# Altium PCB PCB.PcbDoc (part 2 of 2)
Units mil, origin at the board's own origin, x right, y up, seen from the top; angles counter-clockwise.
Board outline 3149.61 x 1968.5 mil, 4 copper layers (Top, GND, Power, Bottom), stack 59.37 mil thick; 127 components, 80 nets, 529 pads, 122 vias.
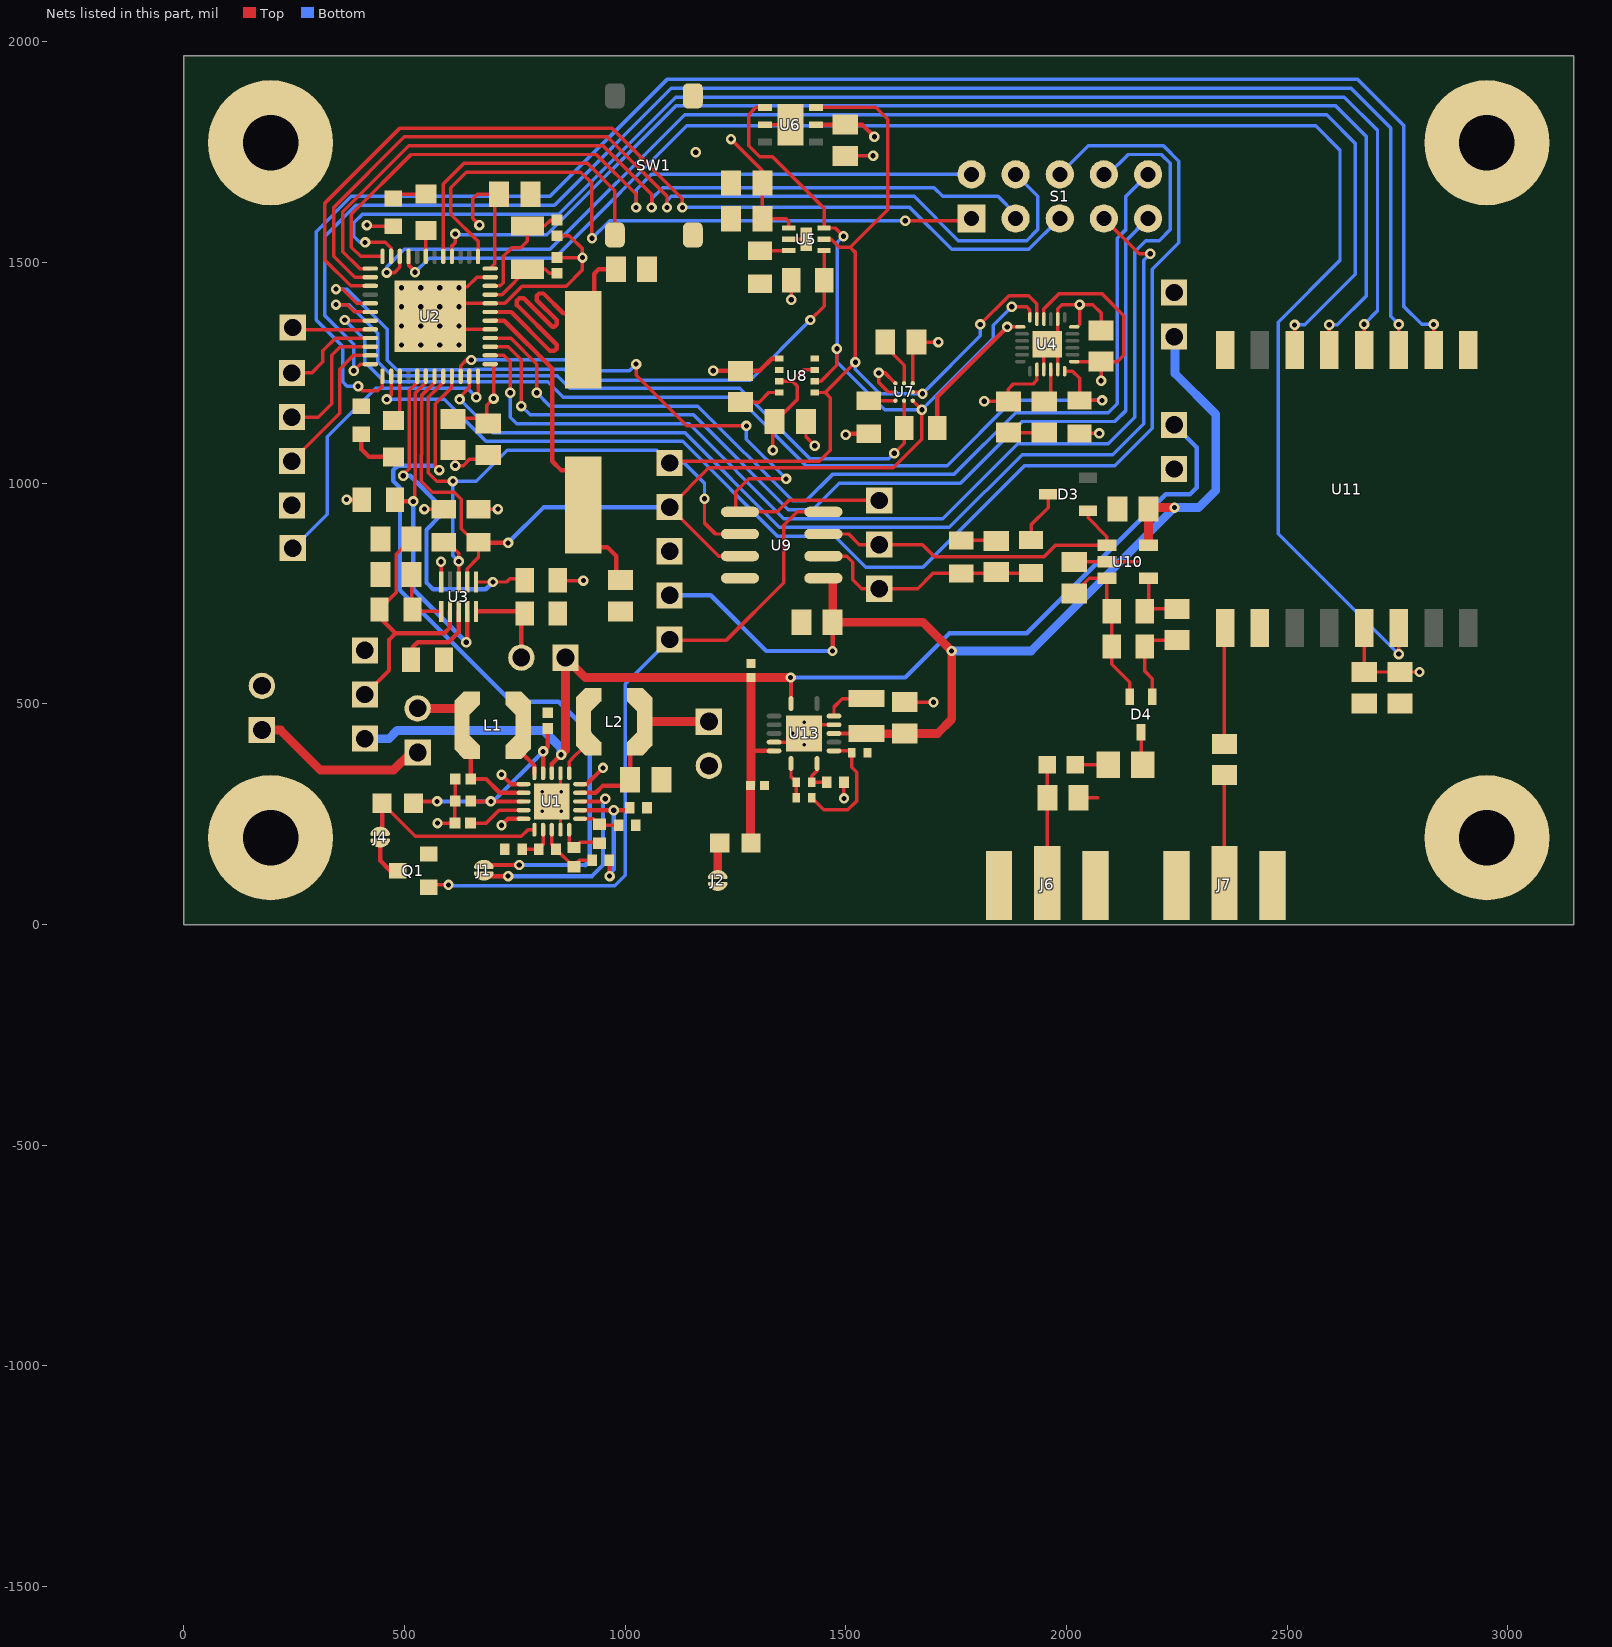
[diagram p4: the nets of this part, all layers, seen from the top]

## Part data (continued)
Rcg1: library part CMP-00129-1, "RES SMD 0.05 OHM 1% 1/3W 0805", Manufacturer="Rohm Semiconductor", Operating Temperature="-55°C ~ 155°C", Package / Case="0805 (2012 Metric)", Power (Watts)="0.333W, 1/3W", Resistance (Ohms)=0.05, Supplier Part Number=RHM1293CT-ND, Temperature Coefficient="0/ +150ppm/°C", Tolerance=±1%
S1: "SIP-5x2 2.54mm 2-row"
SW1: library part CMP-00033-1, "Switch, SPNO Push Button SMD", Manufacturer=APEM
U1: library part CMP-00082-2, "IC ENERGY HARV CTRLR BATT 20VQFN", Current - Supply=488nA, Manufacturer="Texas Instruments", Operating Temperature="-40°C ~ 125°C", Package / Case="20-VFQFN Exposed Pad", Supplier Device Package="20-VQFN (3.5x3.5)", Supplier Part Number=296-37014-2-ND, Voltage - Supply="0.12 V ~ 4 V"
U2: library part CMP-00055-1, "IC MCU 16BIT 64KB FRAM 48VQFN", Manufacturer="Texas Instruments", Operating Temperature="-40°C ~ 85°C (TA)", Package / Case="48-VFQFN Exposed Pad", Supplier Device Package="48-VQFN (7x7)", Supplier Part Number=296-37918-6-ND, Voltage - Supply (Vcc/Vdd)="1.8 V ~ 3.6 V"
U3: library part CMP-00128-1, "IC GAS GAUGE ALARM OUTPUT 10DFN", Manufacturer=STMicroelectronics, Operating Temperature="-40°C ~ 85°C (TA)", Package / Case=10-UFDFN, Supplier Device Package="10-DFN (3x2)", Supplier Part Number=497-15078-2-ND
U4: library part CMP-00238-1, "Accelerometer, Gyroscope, Magnetometer, 3 Axis Sensor I²C, SPI Output", Manufacturer=InvenSense, Operating Temperature="-40°C ~ 85°C (TA)", Supplier Part Number=1428-1019-1-ND
U5: library part CMP-00134-1, "INTEGRATED DIGITAL AMBIENT LIGHT SENSOR WITH INTERRUPT FUNCTION, ODFN-6", Manufacturer=Intersil, Operating Temperature="-40°C ~ 85°C", Package / Case="6-WDFN Exposed Pad", Supplier Device Package="6-ODFN (2.1x2)", Supplier Part Number=ISL29023IROZ-T7TR-ND, Voltage - Supply="2.25 V ~ 3.63 V"
U6: library part CMP-00136-1, "HUMIDITY/TEMPERATURE SENSOR, Accuracy %:2%, Supply Voltage:3V, Humidity Range:0% to 100% Relative Humidity, Sensor Case Style:DFN, No. of Pins:6, Response Time:8s, Operating Temperature Min:-40 C, Operating Temperature Max:125 C , RoHS Compliant", Manufacturer="Sensirion AG", Operating Temperature="-40°C ~ 125°C", Supplier Part Number=1649-1005-2-ND, Voltage - Supply="2.1 V ~ 3.6 V"
U7: library part CMP-0978-00003-2, "Infrared Thermopile Sensor, 2.2 to 3.6 V, 240 uA, -40 to 125 degC, 8-Pin BGA (YZF8), Green (RoHS & no Sb/Br), Tape and Reel", Manufacturer="Texas Instruments", Supply Current (Typ)="240 uA", Supply Voltage="2.2 to 3.6 V", Temperature Range="-40 to 125 degC", Temp Resolution (Max)="14 Bit", Two-Wire Interface Voltage="1.8 V"
U8: library part CMP-00278-1, "PRESSURE HUMIDITY TEMP GAS SENS", Manufacturer="Bosch Sensortec", Operating Pressure="4.35 PSI ~ 15.95 PSI (30 kPa ~ 110 kPa)", Operating Temperature="-40°C ~ 85°C", Package / Case=8-SMD, Supplier Part Number=828-1063-2-ND, Voltage - Supply="1.71 V ~ 3.6 V"
U9: library part CMP-00130-1, "IC MCU 8BIT 3.5KB FLASH 8SOIC", Manufacturer="Microchip Technology", Operating Temperature="-40°C ~ 85°C (TA)", Supplier Device Package=8-SOIC, Supplier Part Number=PIC12LF1552-I/SN-ND, Voltage - Supply (Vcc/Vdd)="1.8 V ~ 3.6 V"
U10: library part CMP-00131-1, "IC OUT COMPARATR NANOPWR SOT23-5", Current - Input Bias (Max)="250pA @ 15V", Current - Output (Typ)=10mA, Current - Quiescent (Max)=1µA, Manufacturer="Texas Instruments", Operating Temperature="0°C ~ 70°C", Package / Case="SC-74A, SOT-753", Supplier Device Package=SOT-23-5, Supplier Part Number=296-13377-2-ND, Voltage - Input Offset (Max)="5mV @ 15V", Voltage - Supply, Single/Dual (±)="2.5 V ~ 16 V, ±1.25 V ~ 8 V"
U11: library part CMP-00138-2, "RF TXRX MODULE ISM<1GHZ", Current - Receiving="10.8mA ~ 12.1mA", Current - Transmitting="20mA ~ 120mA", Frequency=868MHz, Manufacturer="RF Solutions", Operating Temperature="-20°C ~ 70°C", Package / Case="16-SMD Module", Power - Output=17dBm, Supplier Part Number=RFM95W-868S2-ND, Voltage - Supply="1.8 V ~ 3.7 V"
U13: library part CMP-00239-2, "Buck Switching Regulator IC Positive Programmable 1.3V 1 Output 50mA 14-VFQFN Exposed Pad", Current - Output=50mA, Frequency - Switching=2MHz, Manufacturer="Texas Instruments", Operating Temperature="-40°C ~ 85°C (TA)", Package / Case="14-VFQFN Exposed Pad", Supplier Device Package="14-VQFN (3.5x3.5)", Supplier Part Number=296-43622-1-ND, Voltage - Input (Max)=5.5V, Voltage - Input (Min)=2V, Voltage - Output (Max)=5V, Voltage - Output (Min/Fixed)=1.3V
X1 X2 X3 X4 X5 X6 X9 X10 X11 X12 X13 X14 X15 X16 X21 X22 X23: library part CMP-00008-1, "Terminal Assembly, 1 Pin, Vertical, 2.54mm Pitch, Male", Manufacturer=Samtec, Temperature Range="-55 to 125 degC"
X18 X25 X27 X28: library part CMP-00008-2, "Conn Unshrouded Header HDR 1 POS Vertical Solder ST Thru-Hole", Color=Black, Manufacturer="Amphenol FCI", Manufacturer Part Number=68001-101HLF, Supplier Part Number=609-3467-ND
Y1: library part CMP-0447-00001-2, "Crystal, 32.768 kHz, 12.5 pF, -40 to 85 degC, SMD Low Profile 3.2 x 1.5 x 0.9 mm, Tape and Reel", Equivalent Series Resistance (R1)="70 Kohm", Frequency="32.768 kHz", Frequency Tolerance @+25degC="+/- 20 ppm", Insulation Resistance (Min)="500 Mohm", Load Capacitance (CL)="12.5 pF", Manufacturer=Abracon, Operating Temperature="-40 to 85 degC", Q Value (Type)=30000, Shunt Capacitance (C0)="0.9 to 1.2 pF"
Y2: library part CMP-0277-00002-1, "Low Profile Surface Mount Microprocessor Crystal, 4.096 MHz +/-30 ppm, 180 Ohm, -40 to 85 degC, 2-Pin 11.4 x 4.7 x 3.3 mm SMD, RoHS, Tape and Reel", Freq. Stability="+/- 30 ppm", Frequency="4.096 MHz", Load Capacitance="18 pF", Manufacturer=Abracon, Operating Temp. Range="-40 to 85 degC", Shunt Capacitance="7 pF Max."

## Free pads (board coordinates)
  round 0 all layers, no hole paste+0 mask+0: 1(2736.74,-1512.59) 1(2736.74,-1512.59)

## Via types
v1: diameter 23.62, hole 11.81, Top to Bottom, tented both sides, 94 vias
v2: diameter 27.56, hole 11.81, Top to Bottom, tented both sides, 16 vias
v3: diameter 19.68, hole 7.87, Top to Bottom, tented both sides, 8 vias
v4: diameter 23.62, hole 11.81, Top to Bottom, 4 vias

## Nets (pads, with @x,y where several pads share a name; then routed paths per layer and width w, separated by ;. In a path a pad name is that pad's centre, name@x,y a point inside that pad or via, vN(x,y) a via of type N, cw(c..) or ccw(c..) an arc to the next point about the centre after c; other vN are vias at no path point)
ALM: R11.2 U2.29 U3.1 | length 814.3
  Top w7.87: v1(497.23,1016.91) 497.23,1019.12 497.19,1019.16 510.68,1032.65 510.68,1075.29 511.06,1075.66 511.06,1210.45 529,1228.39 U2.29@529,1242.51 ; U3.1@662.24,776.3 v1(700.61,776.3) 731.35,776.3 739.05,784 R11.2@769.6,784
  Bottom w7.87: v1@497.19,1013.11 497.23,1013.15 v1(497.23,1016.91)
  Bottom w10: v1(497.23,1016.91) 513.09,1016.91 579.55,950.45 579.55,924.55 550,895 550,775 565,760 684.31,760 v1(700.61,776.3)
BAT+: C39.2 C40.2 R21.1 U1.18 U13.1 U13.6 X7.1 X23.1 X27.1 | length 3037.4
  Top w10: U1.18@834.05,343.01 834.05,364.05 v1(855,385) ; 1285,395 1286.3,393.7 U13.6@1337.6,393.7 ; v4(1375,560) 1375.98,559.02 U13.1@1375.98,500.98
  Top w20: v1(855,385) 865,395 X7.1@865,605 910,560 C40.2@1285,560 ; R21.1@1285.43,185 1284.25,186.18 C39.2@1284.25,315 1285,315.75 1285,395 C40.2@1285,560 ; v4(1375,560) C40.2@1285,560
  Bottom w10: v4(1375,560) 1635,560 1735,660 1910,660 2225,975 2280,975 2295,990 2295,1081.38 X27.1@2244.09,1132.28
  Bottom w20: X23.1@410.24,421.26 465,421.26 483.74,440 815,440 855,400 v1(855,385)
BAT-: Rcg1.2 U3.10 X7.2 | length 238.5
  Top w10: U3.10@662.24,709.76 767.83,709.76 Rcg1.2@772.6,705 765,697.4 X7.2@765,605 765,595.63 X7.2@755.31,605.31
BUCK_EN: Q1.1 U9.4 X16.1 | length 1579.9
  Top w7.87: Q1.1@555,85 560,90 v1(600,90) ; X16.1@1100.92,646.05 1100.92,644.84 1229.84,644.84 1360,775 1360,905.14 1389.91,935.06 U9.4@1449.4,935.06
  Bottom w7.87: v1(600,90) 601.75,88.25 976.75,88.25 1000,111.5 1000,545.13 X16.1@1100.92,646.05
DATA: D3.1 U9.3 U10.1 X10.1 | length 769.7
  Top w7.87: U9.3@1449.4,885.06 1506.91,885.06 1530.91,861.06 X10.1@1575.91,861.06 1673.91,861.06 1700.91,834.06 1949.91,834.06 1975.31,859.46 U10.1@2091.67,859.46 2091.67,879.3 2049.19,921.78 D3.1@2049.19,937.65
GND: C1.1 C2.1 C3.1 C4.1 C5.1 C6.1 C7.1 C8.1 C9.2 C10.2 C11.1 C12.1 C13.2 C14.1 C15.2 C16.1 C17.1 C18.2 C19.1 C22.2 C25.2 C26.2 C27.2 C28.1 C29.1 C31.1 C32.1 C33.1 C34.1 C35.2 C36.2 C39.1 C40.1 C41.1 D4.1 J2.2 J6.2 J6.3 J6.4 J6.5 J7.2 J7.3 J7.4 J7.5 M1.1 M2.1 M3.1 M4.1 Q1.2 R5.1 R6.1 R7.1 R8.2 R9.2 R15.1 R19.1 R25.1 R26.1 R32.1 R33.1 Rcg1.1 SW1.1 SW1.2 U1.1 U1.5 U1.9 U1.15 U1.17 U1.21 U2.36 U2.41 U2.44 U2.47 U2.49 U3.5 U4.9 U4.11 U4.18 U4.20 U4.25 U5.2 U5.7 U6.2 U6.7 U7.A1 U7.A2 U7.B1 U8.1 U8.5 U8.7 U9.8 U10.2 U11.1 U11.8 U11.10 U13.5 U13.12 U13.15 X6.1 X8.2 X14.1 X28.1 | length 3919
  Top w7.87: v1(415,1585) 417.72,1582.28 R8.2@474.53,1582.28 ; U2.49@558.53,1378.34 U2.49@588.05,1407.87 ; v1(575,230) C3.1@614.57,230 614.57,279.57 C2.1@615,280 C4.1@615,330 ; v1(583,822) 583,776.8 U3.5@583.5,776.3 ; U2.49@588.05,1348.81 U2.41@694.35,1348.81 ; C8.1@606.67,1091.34 615,1083.01 v1(615,1040) 633,1040 647,1054 673,1054 C7.1@687,1068 ; v2(623.49,1443.3) U2.49@588.05,1407.87 ; U2.49@625.19,1445 642.49,1445 664.41,1466.92 U2.47@694.35,1466.92 ; v1(663,1195) 666.79,1198.79 U2.36@666.79,1242.51 ; U1.1@770.07,317.42 U1.1@770.07,318.4 ; C9.2@845.81,1511.49 v1(903.51,1511.49) ; C10.2@845.81,1561.05 873.81,1561.05 903.51,1531.35 v1(903.51,1511.49) ; U1.9@853.73,215.06 U1.21@853.73,259.35 ; U1.21@853.73,298.72 U1.17@853.73,343.01 ; U1.15@898.02,317.42 U1.15@898.02,318.4 ; C27.2@1261.87,1184 1304,1184 1325.71,1205.71 U8.5@1349.41,1205.71 ; U6.2@1317.39,1812.43 U6.7@1374.87,1812.43 ; U13.5@1337.6,413.39 U13.15@1385.82,413.39 ; U8.7@1344.35,1256.89 U8.7@1349.41,1256.89 ; U5.2@1370.89,1552.87 U5.7@1410.85,1552.87 ; C26.2@1410,1140 1410,1105 v1(1430,1085) ; U13.15@1425.19,452.76 U13.12@1473.42,452.76 ; v1(1496.06,286.06) R33.1@1496.06,322.84 ; C25.2@1498.87,1742 v1(1562,1742) ; C22.2@1589.57,1320 1589.57,1310.43 1632.21,1267.79 U7.A2@1632.21,1226.56 ; U7.B1@1612.53,1206.87 1596.43,1206.87 1575,1228.31 v1(1575,1250) 1589.09,1250 U7.A1@1612.53,1226.56 ; C41.1@1633.86,503.94 v1(1698.94,503.94) ; R25.1@1761.91,870.46 1839.94,870.46 C31.1@1840.91,869.49 ; C15.2@1868.87,1115 C19.1@1950.05,1115 ; U4.9@1948.82,1257.87 1948.82,1307.09 U4.25@1956.69,1314.96 U4.25@1962.6,1320.87 ; U4.11@1980.32,1257.87 1980.32,1303.15 U4.25@1962.6,1320.87 ; U4.18@2017.72,1354.33 2024.33,1354.33 2030,1360 v4(2030,1405) ; C34.1@2017.91,821.49 C34.1@2020.51,818.9 ; C34.1@2018.48,822.06 U10.2@2091.67,822.06 2161.63,822.06 ; C32.1@2027.56,287.4 2070.87,287.4 ; C16.1@2078.74,1346.46 2078.74,1385.83 2059.57,1405 v4(2030,1405) ; C29.1@2115.48,942.06 C29.1@2118.11,944.69 ; D4.1@2194.88,516.73 2194.88,557.09 2177.4,574.57 R26.1@2177.4,630 2192.03,644.62 C33.1@2250.91,644.62 ; U11.10@2437.01,673.02 U11.10@2438.4,671.62 ; U2.49@588.05,1407.87 U2.44@694.35,1407.87 727.87,1407.87 766.49,1446.49 866.49,1446.49 903.51,1483.51 v1(903.51,1511.49) ; U4.25@1962.6,1320.87 1980.32,1338.58 U4.20@1980.32,1372.05 1980.32,1395.31 1990,1405 v4(2030,1405)
  Top w10: v1(720,225) 734.66,239.66 U1.5@770.07,239.66 ; v1(720,340) 741.6,318.4 U1.1@770.07,318.4 ; U1.15@898.02,318.4 913.4,318.4 v1(950,355)
  Bottom w7.87: X6.1@247,853 248,853 325,930 325,1105 435,1215 643,1215 v1(663,1195)
  other v1: 1160,1750
  other v2: 493.57,1313.38 536.87,1313.38 580.18,1313.38 623.49,1313.38 493.57,1356.69 536.87,1356.69 580.18,1356.69 623.49,1356.69 493.57,1399.99 536.87,1399.99 580.18,1399.99 623.49,1399.99 493.57,1443.3 536.87,1443.3 580.18,1443.3
  other v3: 812.39,257.38 855.7,257.38 812.39,300.69 855.7,300.69 1405.51,407.48 1379.92,433.07 1431.1,433.07 1405.51,458.66
HIGHFCLOCK_IN: C11.2 U2.42 Y2.1 | length 722.9
  Top w10: U2.42@694.35,1368.5 726.5,1368.5 835,1260 835,1050 855,1030 Y2.1@910,1030 ; Y2.1@875.98,980 Y2.1@905,950.98 Y2.1@905,905 ; Y2.1@890,855 960,855 980,835 980,790.43 C11.2@990,780.43
HIGHFCLOCK_OUT: C12.2 U2.43 Y2.2 | length 889.4
  Top w10: U2.43@694.35,1388.18 741.82,1388.18 830,1300 840,1300 845,1305 845,1313.88 755,1403.88 755,1413.88 760.56,1419.44 770.56,1419.44 835,1355 840,1355 845,1360 845,1370 800,1415 800,1425 805,1430 815,1430 860,1385 Y2.2@915,1385 ; Y2.2@905,1325 930,1350 930,1475 940,1485 C12.2@979.13,1485
LORA_DIO0: U2.9 U11.14 | length 3672.6
  Top w7.87: U2.9@509.31,1514.17 509.31,1494.56 524,1479.87 v1(524,1478) ; v1@2753,610.8 v1(2753,613) 2753.36,613.36 U11.14@2753.36,671.62
  Bottom w7.87: v1(524,1478) 556,1510 840,1510 1140,1810 2565,1810 2620,1755 2620,1505 2480,1365 2480,886 v1(2753,613)
LORA_RESET: U2.10 U11.6 | length 2975.6
  Top w7.87: v1(460,1477.49) 477.49,1477.49 489.63,1489.63 U2.10@489.63,1514.17 ; U11.6@2517.14,1301.54 v1(2517.14,1358.86)
  Bottom w7.87: v1(460,1477.49) 460,1490 500,1530 830,1530 1135,1835 2590,1835 2655,1770 2655,1473.74 2540.12,1358.86 v1(2517.14,1358.86)
LOWFCLOCK_IN: C9.1 U2.45 Y1.1 | length 178.9
  Top w7.87: U2.45@694.35,1427.55 721.12,1427.55 Y1.1@778.53,1484.96 819.34,1484.96 828.24,1476.06 C9.1@845.81,1476.06
LOWFCLOCK_OUT: C10.1 U2.46 Y1.2 | length 268.3
  Top w7.87: U2.46@694.35,1447.24 716.56,1447.24 724.12,1454.8 724.12,1514.17 743.72,1533.77 763.53,1533.77 778.53,1548.77 Y1.2@778.53,1583.39 818.14,1583.39 831.24,1596.49 C10.1@845.81,1596.49
NetC3_2: C3.2 U1.4 | length 132.2
  Top w7.87: C3.2@650,230 685,230 714.35,259.35 U1.4@770.07,259.35
NetC4_2: C4.2 H_IN.2 L1.1 U1.2 | length 328.4
  Top w7.87: L1.1@629.39,451.03 L1.1@630.39,452.03
  Top w10: L1.1@647.14,405.89 650.43,402.6 C4.2@650.43,330 685,330 716.28,298.72 U1.2@770.07,298.72
  Top w20: H_IN.2@530,490 L1.1@647.14,490
NetC5_2: C5.2 L2.2 U1.14 X19.1 | length 366.8
  Top w10: U1.14@898.02,298.72 933.72,298.72 950,315 998.41,315 C5.2@1011.44,328.03 1011.44,389.23 L2.2@1017.92,395.71
  Top w20: L2.2@1040.36,457.03 1043.33,460 X19.1@1190,460 X19.1@1210,460
NetC13_1: C13.1 R14.1 U3.6 | length 138
  Top w7.87: R14.1@516.31,716 C13.1@516.31,793.03 ; R14.1@522.54,709.76 U3.6@583.5,709.76
NetC14_2: C14.2 R14.2 U3.7 X22.1 | length 592.2
  Top w7.87: R14.2@443.47,714.03 481.87,752.43 481.87,839.6 C14.2@516.31,874.03
  Top w10: X22.1@410.24,521.26 465,576.02 465,645 480,660 ; R14.2@443.47,714.03 443.47,696.53 480,660 ; U3.7@603.19,709.76 603.19,673.19 590,660 480,660
NetC19_2: C19.2 U4.10 | length 77.9
  Top w7.87: C19.2@1964.57,1180 U4.10@1964.57,1257.87
NetC30_1: C30.1 D4.3 | length 73.8
  Top w7.87: C30.1@2169.29,362.2 D4.3@2169.29,436.02
NetC30_2: C30.2 L3.2 | length 78.7
  Top w7.87: L3.2@2019.69,362.2 C30.2@2094.49,362.2 C30.2@2098.43,362.2
NetC32_2: C32.2 J6.1 L3.1 | length 267.7
  Top w7.87: J6.1@1956.69,94.49 C32.2@1956.69,287.4 L3.1@1956.69,362.2
NetC34_2: C34.2 D4.2 R24.2 R26.2 U10.3 | length 377.3
  Top w7.87: C34.2@2017.91,750.62 2051.94,784.65 U10.3@2091.67,784.65 2091.67,720.93 R24.2@2102.6,710 R26.2@2102.6,630 2102.6,590.31 2143.7,549.21 D4.2@2143.7,516.73
NetC38_1: C38.1 J7.1 | length 244.1
  Top w7.87: J7.1@2358.27,94.49 C38.1@2358.27,338.58
NetC38_2: C38.2 U11.9 | length 260.8
  Top w7.87: C38.2@2358.27,409.45 U11.9@2358.27,670.23
NetD1_1: D1.1 R8.1 | length 70.2
  Top w7.87: R8.1@478.46,1655.11 D1.1@548.68,1655.11
NetD1_2: D1.2 U2.7 | length 58.3
  Top w7.87: U2.7@548.68,1514.17 D1.2@548.68,1572.43
NetD2_1: D2.1 R9.1 | length 113.5
  Top w10: R9.1@402.49,1111.28 402.49,1077.51 420,1060 D2.1@475,1060
NetD2_2: D2.2 U2.27 | length 105.9
  Top w7.87: D2.2@475,1142.68 489.63,1157.31 U2.27@489.63,1242.51
NetD3_3: D3.3 R23.1 | length 119.6
  Top w7.87: R23.1@1919.91,871.46 1919.91,906.06 1958.64,944.78 D3.3@1958.64,975.06
NetJ1_1: J1.1 U2.33 | length 1731.4
  Top w8: v1(579,1030) 570,1039 570,1180 607.74,1217.74 U2.33@607.74,1242.51
  Top w10: J1.1@670,134.61 670.39,135 v1(760,135)
  Bottom w10: v1(579,1030) 569,1040 485,1040 474.42,1029.42 474.42,1005.58 490,990 490,757.74 742.74,505 850,505 920,435 920,145 909.61,134.61 909.21,135 v1(760,135)
NetJ1_2: J1.2 U1.13 | length 501.9
  Top w10: J1.2@670,110 J1.2@680,110 v1(735,110) ; U1.13@898.02,279.03 949.03,279.03 v1(955,285)
  Bottom w10: v1(735,110) 925,110 950,135 950,280 v1(955,285)
NetJ2_1: J2.1 R21.2 | length 73.6
  Top w20: J2.1@1210,113.29 1210,180.43 R21.2@1214.57,185
NetJ4_1: J4.1 R20.2 U1.6 | length 447.7
  Top w7.87: J4.1@445,211.57 J4.1@449.57,216.14 ; R20.2@449.57,275 524.57,200 765,200 780.06,215.06 U1.6@794.68,215.06
  Top w10: J4.1@449.57,216.14 R20.2@449.57,275
NetJ4_2: J4.2 Q1.3 | length 89.6
  Top w10: J4.2@445,185.1 J4.2@445,185 445,145 468,122 Q1.3@485,122
NetL1_2: L1.2 U1.20 | length 77.7
  Top w10: L1.2@746.92,390.71 764.29,390.71 794.68,360.32 U1.20@794.68,343.01
NetL2_1: L2.1 U1.16 | length 72.8
  Top w7.87: U1.16@873.42,343.01 873.42,369.23 880.56,376.37 880.56,376.76 L2.1@906.07,402.27
NetL5_1: L5.1 U13.13 | length 102.4
  Top w7.87: U13.13@1473.42,472.44 1473.42,493.11 1492.52,512.21 L5.1@1547.24,512.21
NetR1_1: R1.1 R6.2 U1.12 | length 304.1
  Top w10: U1.12@898.02,259.35 v1(974.35,259.35) 1004.66,259.35 R6.2@1010.31,265 ; R1.1@964.56,146.03 965,145.59 v1(965,110)
  Bottom w10: v1(965,110) 965,116.16 974.35,125.51 v1(974.35,259.35)
NetR1_2: R1.2 R2.2 R3.2 U1.8 | length 134.4
  Top w7.87: R2.2@834.05,180.54 U1.8@834.05,215.06 ; R2.2@843.56,171.03 R3.2@881.24,133.35 ; R3.2@883.87,133.35 896.56,146.03 R1.2@925.19,146.03
NetR2_1: R2.1 R5.2 U1.7 | length 85.9
  Top w7.87: R5.2@766.56,171.03 R2.1@804.19,171.03 814.36,181.21 U1.7@814.36,215.06
NetR3_1: R3.1 R4.2 U1.10 | length 110.2
  Top w7.87: U1.10@873.42,215.06 873.42,183.17 883.87,172.72 897.33,186.17 R4.2@941.87,186.17
NetR4_1: R4.1 R7.2 U1.11 | length 90
  Top w7.87: U1.11@898.02,239.66 927.76,239.66 941.87,225.54 R7.2@982.13,225.54
NetR15_2: R15.2 U3.8 | length 203
  Top w10: R15.2@518.47,591.03 518.47,628.47 530,640 600,640 622.87,662.87 U3.8@622.87,709.76
NetR16_2: R16.2 U7.C1 | length 60.3
  Top w7.87: R16.2@1552.23,1187.19 U7.C1@1612.53,1187.19
NetR17_1: R17.1 U2.19 U4.12 | length 2142.9
  Top w7.87: v1(365,1370) 366.5,1368.5 U2.19@422.7,1368.5 ; U4.12@1996.06,1253.94 2013.78,1253.94 2029.87,1237.84 R17.1@2029.87,1187.83 v1(2080.85,1187.83)
  Bottom w7.87: v1(365,1370) 410,1325 410,1274.83 454.9,1229.94 825.06,1229.94 860,1195 1255,1195 1410,1040 1730,1040 1877.83,1187.83 v1(2080.85,1187.83)
NetR18_1: R18.1 U2.17 U5.4 | length 1519.3
  Top w7.87: v1(345,1440) 360,1440 392.13,1407.87 U2.17@422.7,1407.87 ; v1(1420,1370) 1451.28,1401.28 R18.1@1451.28,1460.43 ; R18.1@1450.81,1460.89 U5.4@1450.81,1527.28
  Bottom w7.87: v1(345,1440) 370,1440 461.19,1348.81 461.19,1278.81 482.31,1257.69 660.36,1257.69 660.68,1258 862,1258 886.75,1233.25 1283.25,1233.25 v1(1420,1370)
NetR19_2: R19.2 U5.3 | length 64.6
  Top w7.87: R19.2@1306.32,1527.28 U5.3@1370.89,1527.28
NetR22_2: R22.2 U2.18 U7.C2 | length 1665.6
  Top w7.87: v1(345,1405) 370.76,1405 387.58,1388.18 U2.18@422.7,1388.18 ; v1(1610,1068) 1632.47,1090.47 R22.2@1632.47,1125.43 ; R22.2@1632.21,1125.69 U7.C2@1632.21,1187.19
  Bottom w7.87: v1(345,1405) 375,1405 440,1340 440,1275 471.19,1243.81 846.19,1243.81 875,1215 1260,1215 1419.13,1055.87 1597.87,1055.87 v1(1610,1068)
NetR30_1: R30.1 R32.2 U13.9 | length 273.6
  Top w7.87: R30.1@1423.23,287.4 1450.63,260 1505,260 1525,280 1525,345 1513.78,356.22 R32.2@1513.78,389.77 ; U13.9@1473.42,393.7 R32.2@1509.85,393.7 ; R32.2@1516.73,386.81 R32.2@1517.72,385.83
NetR30_2: R30.2 R31.2 U13.7 | length 82.6
  Top w7.87: U13.7@1375.98,365.16 1375.98,334.65 R31.2@1387.8,322.84 R30.2@1387.8,287.4
NetR31_1: R31.1 R33.2 U13.8 | length 80.7
  Top w7.87: U13.8@1435.04,365.16 1435.04,348.43 1423.23,336.62 R31.1@1423.23,322.84 R33.2@1456.69,322.84
NetS1_1: S1.1 U2.1 | length 1527
  Top w7.87: U2.1@666.79,1514.17 666.79,1548.21 605,1610 605,1670 640,1705 900,1705 925,1680 v1@925,1565 ; v1(925,1555) v1@930,1560 ; v1(1635,1595) 1780,1595 S1.1@1785,1600
  Bottom w7.87: v1(925,1555) 965,1595 v1(1635,1595)
NetS1_2: S1.2 U2.12 | length 1726.6
  Top w7.87: U2.12@450.26,1514.17 400.83,1514.17 380,1535 380,1610 515,1745 935,1745 1025,1655 v1(1025,1625)
  Bottom w7.87: v1@1025,1635 1025,1665 1060,1700 S1.2@1785,1700
NetS1_3: S1.3 U2.13 | length 1896.5
  Top w7.87: U2.13@422.7,1486.61 398.39,1486.61 360,1525 360,1615 510,1765 950,1765 1060,1655 v1(1060,1625)
  Bottom w7.87: v1(1060,1625) 1060,1645 1085,1670 1700,1670 1720,1650 1845,1650 1885,1610 S1.3@1885,1600
NetS1_4: S1.4 U2.14 | length 2171.7
  Top w7.87: U2.14@422.7,1466.92 387.7,1466.92 340,1514.62 340,1625 500,1785 960,1785 1095,1650 v1(1095,1625)
  Bottom w7.87: v1(1095,1625) 1095,1640 1105,1650 1655,1650 1755,1550 1910,1550 1935,1575 1935,1650 S1.4@1885,1700
NetS1_5: S1.5 U2.15 | length 2146.3
  Top w7.87: U2.15@422.7,1447.24 378.38,1447.24 320,1505.62 320,1635 490,1805 970,1805 1130,1645 v1(1130,1625)
  Bottom w7.87: v1(1130,1625) 1645,1625 1740,1530 1915,1530 S1.5@1985,1600
NetS1_6: S1.6 U2.26 | length 3020.8
  Top w7.87: v1(460,1190) 469.94,1199.94 U2.26@469.94,1242.51
  Bottom w7.87: v1(460,1190) 590,1190 685,1095 1130.38,1095 1345.38,880 1475,880 1545,810 1675,810 1905,1040 2110,1040 2195,1125 2195,1485 2255,1545 2255,1730 2220,1765 2050,1765 S1.6@1985,1700
NetS1_7: S1.7 U2.35 | length 2358.5
  Top w7.87: v1(625,1190) 625,1195 647.11,1217.11 U2.35@647.11,1242.51 ; S1.7@2085,1600 2165,1520 v1(2190,1520)
  Bottom w7.87: v1(625,1190) 700,1115 1135,1115 1349.48,900.52 1609.56,900.52 1610.08,900 1735,900 1900,1065 2105,1065 2175,1135 2175,1505 v1(2190,1520)
NetS1_8: S1.8 U2.38 | length 2584.9
  Top w7.87: U2.38@694.35,1289.76 725.24,1289.76 740,1275 v1(740,1205)
  Bottom w7.87: v1(740,1205) 740,1150 755,1135 1145,1135 1360,920 1720,920 1890,1090 2095,1090 2155,1150 2155,1525 2180,1550 2210,1550 2235,1575 2235,1725 2215,1745 2140,1745 2095,1700 S1.8@2085,1700
NetS1_9: S1.9 U2.39 | length 2204.5
  Top w7.87: U2.39@694.35,1309.44 735.56,1309.44 765,1280 v1(765,1175)
  Bottom w7.87: v1(765,1175) 785,1155 1155,1155 1370,940 1425,940 1485.52,1000.52 1609.56,1000.52 1610.08,1000 1760,1000 1900,1140 2110,1140 2135,1165 2135,1550 S1.9@2185,1600
NetS1_10: S1.10 U2.40 | length 2251.7
  Top w7.87: U2.40@694.35,1329.13 740.87,1329.13 800,1270 v1(800,1205)
  Bottom w7.87: v1(800,1205) 830,1175 1165,1175 1380,960 1410,960 1470,1020 1745,1020 1885,1160 2095,1160 2115,1180 2115,1555 2135,1575 2135,1650 S1.10@2185,1700
NetSW1_4: SW1.4 U2.5 | length 704.1
  Top w7.87: U2.5@588.05,1514.17 588.05,1678.05 635,1725 915,1725 976.81,1663.19 SW1.4@976.81,1562.52 SW1.4@982.52,1562.52
NetU2_4: U2.4 U11.5 | length 2798.4
  Top w7.87: U2.4@607.74,1514.17 607.74,1537.74 615,1545 v1(615,1565) ; U11.5@2595.88,1301.54 v1(2595.88,1359.12)
  Bottom w7.87: v1(615,1565) 616.75,1563.25 822.87,1563.25 1114.62,1855 2610,1855 2680,1785 2680,1425 2614.12,1359.12 v1(2595.88,1359.12)
NetU2_11: U2.11 U11.4 | length 3125.1
  Top w7.87: v1(411,1545.86) 457.02,1545.86 469.94,1532.93 U2.11@469.94,1514.17 ; U11.4@2674.62,1301.54 v1(2674.62,1360.16)
  Bottom w7.87: v1(411,1545.86) 399.14,1545.86 385,1560 385,1590 405,1610 850,1610 1115,1875 2630,1875 2705,1800 2705,1390.54 v1(2674.62,1360.16)
NetU2_20: U2.20 X1.1 | length 176.2
  Top w7.87: X1.1@247,1348.81 247.56,1348.25 422.14,1348.25 U2.20@422.7,1348.81
NetU2_21: U2.21 X2.1 | length 225.1
  Top w8: X2.1@245,1250 290,1250 315,1275 315,1300 344.13,1329.13 U2.21@422.7,1329.13
NetU2_22: U2.22 X3.1 | length 308.2
  Top w7.87: X3.1@245,1150 305,1150 335,1180 335,1290 354.44,1309.44 U2.22@422.7,1309.44
NetU2_23: U2.23 X4.1 | length 335.6
  Top w7.87: X4.1@245,1050 353.59,1158.59 353.59,1258.59 384.76,1289.76 U2.23@422.7,1289.76
NetU2_24: U2.24 U11.3 | length 3478
  Top w7.87: v1(385,1255) 400.07,1270.07 U2.24@422.7,1270.07 ; U11.3@2753.36,1301.54 v1(2753.36,1359.9)
  Bottom w7.87: v1(385,1255) 385,1315 320,1380 320,1560 390,1630 840,1630 1105,1895 2645,1895 2735,1805 2735,1378.27 v1(2753.36,1359.9)
NetU2_25: U2.25 U11.2 | length 3693.5
  Top w7.87: v1(395,1220) 405,1210 440,1210 450.26,1220.26 U2.25@450.26,1242.51 ; U11.2@2832.1,1301.54 v1(2832.1,1360.06)
  Bottom w7.87: v1(395,1220) 370,1220 360,1230 360,1310 300,1370 300,1570 380,1650 830,1650 1095,1915 2660,1915 2765,1810 2765,1400 2804.94,1360.06 v1(2832.1,1360.06)
RF_DEM: C33.2 R24.1 U10.4 | length 136.5
  Top w7.87: U10.4@2186.16,784.65 2186.16,722.83 2191.19,717.8 R24.1@2191.19,715.49 ; R24.1@2191.19,710 R24.1@2191.19,715.49 ; C33.2@2250.91,715.49 R24.1@2191.19,715.49
RSTIO: R10.2 U2.30 U3.9 | length 789.7
  Top w7.87: v1(519.87,959.03) 523.87,959.03 523.87,1007.41 524.56,1008.09 524.56,1069.54 524.94,1069.92 524.94,1204.64 548.68,1228.39 U2.30@548.68,1242.51 ; v1@638.53,640 v1(640,640)
  Top w10: R10.2@478.4,963 482.37,959.03 v1(519.87,959.03) ; v1@638.53,640 642.56,644.02 U3.9@642.56,709.76
  Bottom w7.87: v1@632.9,640 v1(640,640)
  Bottom w10: v1(519.87,959.03) 519.87,760.13 v1(640,640)
SCLK: R12.1 U2.32 U3.3 U4.23 U5.5 U6.6 U7.B3 U8.4 U9.6 X12.1 | length 3496.4
  Top w7.87: 574.47,1214.86 554.32,1194.71 554.32,1023.92 573.24,1005 v1(610,1005) ; 574.52,1214.86 588.05,1228.39 U2.32@588.05,1242.51 ; R12.1@588.87,866.63 597.94,866.63 622.87,841.69 U3.3@622.87,776.3 ; X12.1@1100.92,1044 1106.92,1050 1440,1050 1465,1075 1465,1193.98 1453.28,1205.71 ; v1(1180,965) 1180,910 1204.94,885.06 U9.6@1260.42,885.06 ; U8.4@1430.12,1205.71 1453.28,1205.71 ; U6.6@1432.35,1851.8 1568.2,1851.8 1595,1825 1595,1620 1510,1535 ; U5.5@1450.81,1552.87 1467.13,1552.87 1485,1535 1510,1535 ; U7.B3@1651.9,1206.87 1670.13,1206.87 v1(1674,1203) ; v1(1805,1360) 1870,1425 1915,1425 1933.07,1406.93 U4.23@1933.07,1372.05 ; 1453.28,1205.71 v1(1522,1274.43) 1522,1525 1520,1525 1510,1535
  Bottom w7.87: v1(623,823) 610,836 v1(610,1005) 662.84,1005 732.84,1075 1071.98,1075 X12.1@1100.92,1046.05 1133.95,1046.05 1180,1000 v1(1180,965) ; v1@1524.65,1277.09 v1(1522,1274.43) 1522,1258 1577,1203 v1(1674,1203) 1805,1334 v1(1805,1360)
SDATA: R13.1 U2.31 U3.2 U4.24 U5.6 U6.1 U7.C3 U8.3 U9.7 X13.1 | length 3430.2
  Top w7.87: U2.31@568.37,1242.51 568.37,1228.39 538.81,1198.83 538.81,1064.17 538.53,1063.89 538.53,1004.52 563.04,980 612.59,980 626.37,966.22 626.37,966.08 628.45,964 628.87,964 628.87,897.03 R13.1@659.28,866.63 ; U3.2@642.56,776.3 642.56,806.72 667.87,832.03 R13.1@667.87,865 ; U9.7@1260.42,835.06 1211.92,835.06 X13.1@1100.92,946.05 1189.87,1035 1607.91,1035 1672.57,1099.65 v1(1672.57,1166.52) U7.C3@1651.9,1187.19 ; U6.1@1317.39,1851.8 1296.8,1851.8 1280,1835 1280,1765 1305,1740 1334,1740 1450.81,1623.19 U5.6@1450.81,1578.46 1476.54,1578.46 v1(1495,1560) ; U8.3@1428.15,1231.3 U8.3@1430.12,1231.3 1443.9,1231.3 1480,1267.4 v1(1480,1305) ; v1(1876.38,1400) 1910,1400 1917.32,1392.68 U4.24@1917.32,1375.98
  Top w10: R13.1@659.28,866.63 660.9,865 667.87,865 v1(735,865)
  Bottom w7.87: v1(1480,1305) 1480,1275 1588.48,1166.52 v1(1672.57,1166.52) 1834.65,1328.6 1834.65,1358.27 v1(1876.38,1400) ; v1@1481,1306 1481,1546 v1(1495,1560)
  Bottom w10: v1(735,865) 816.05,946.05 X13.1@1100.92,946.05
SI: U2.34 U9.5 X11.1 | length 1425.1
  Top w7.87: U2.34@627.42,1242.51 627.42,1266.16 640.69,1279.43 v1(651.35,1279.43) ; v1(1025,1270) 1025,1245 1140,1130 v1(1275,1130) ; v1(1365,1010) 1280,1010 1251,981 1251,944.48 U9.5@1260.42,935.06 1344.91,935.06 1370.91,961.06 X11.1@1575.91,961.06
  Bottom w7.87: v1(651.35,1279.43) 870.57,1279.43 895,1255 1010,1255 v1(1025,1270) ; v1(1275,1130) 1275,1100 v1(1365,1010)
SOLAR+: H_IN.1 X8.1 | length 407.1
  Top w20: X8.1@177.17,440.94 219.06,440.94 310,350 475,350 515,390 H_IN.1@530,390
VCC: C6.2 C7.2 C8.2 C15.1 C16.2 C17.2 C18.1 C22.1 C25.1 C26.1 C27.1 C35.1 C36.1 R10.1 R11.1 R12.2 R13.2 R16.1 R17.2 R18.2 R22.1 U2.37 U2.48 U4.1 U4.8 U4.13 U4.22 U5.1 U6.5 U7.A3 U8.2 U8.6 U8.8 U11.13 X5.1 X18.1 X19.2 X21.1 | length 3086.3
  Top w7.87: v1(369,963) R10.1@403.6,963 ; v1(545.41,941.43) R12.2@588.87,941.43 ; C8.2@606.67,1162.2 621.88,1147 678.87,1147 687,1138.87 687,1177 v1(702,1192) 702,1270 702.07,1270.07 U2.37@694.35,1270.07 ; R13.2@667.87,941.43 v1(711.87,941.43) ; v1(670,1585) 655,1600 655,1645 665,1655 C6.2@705,1655 ; U2.48@694.35,1486.61 705,1497.25 C6.2@705,1655 ; C6.2@714.57,1655 C6.2@705,1655 ; R11.1@844.4,784 848.87,779.53 v1(905.51,779.53) ; v1(1240,1780) 1311.31,1708.69 C18.1@1311.31,1680.43 C17.2@1311.31,1599.43 1364.87,1599.43 1370.89,1593.41 U5.1@1370.89,1578.46 ; v1(1335,1075) 1335,1124.99 1337.44,1127.43 1337.44,1137.44 1389.76,1189.76 1389.76,1220.47 1378.94,1231.3 ; U8.6@1358.27,1231.3 1378.94,1231.3 ; v1(1376.47,1416.03) R18.2@1376.47,1460.43 ; U8.2@1421.26,1256.89 1404.53,1256.89 1378.94,1231.3 ; U7.A3@1651.9,1226.56 1651.9,1311.46 C22.1@1660.43,1320 v1(1710,1320) ; v1(1814.13,1185.87) C15.1@1868.01,1185.87 ; v1(1866.14,1354.33) U4.1@1895.67,1354.33 ; C15.1@1868.87,1185.87 C15.1@1868.01,1185.87 ; U4.8@1933.07,1257.87 1933.07,1233.07 1925,1225 1880,1225 1868.01,1213.01 C15.1@1868.01,1185.87 ; U4.22@1948.82,1372.05 1948.82,1394.99 1983.83,1430 2080,1430 2130,1380 2130,1290 2115.59,1275.59 C16.2@2078.74,1275.59 ; U4.13@2017.72,1275.59 C16.2@2078.74,1275.59 ; R17.2@2029.87,1113.03 v1(2074.47,1113.03) ; v1(2078.74,1232.28) C16.2@2078.74,1275.59 ; C36.1@2674.62,572.54 U11.13@2674.62,671.62 ; C36.1@2674.8,572.36 C35.1@2755.8,572.36 v1(2800.24,572.36)
  Top w10: v1(1200,1255) 1200.13,1254.87 C27.1@1261.87,1254.87 1304.87,1254.87 1332.48,1282.48 U8.8@1349.41,1282.48 ; U6.5@1432.35,1812.43 1498.44,1812.43 C25.1@1498.87,1812.87 1537.13,1812.87 v1(1565,1785) ; v1(1500,1110) 1499.06,1110 1497.03,1112.03 R16.1@1551.87,1112.03 ; R22.1@1707.28,1125.43 1707.28,1195.46 v1(1866.14,1354.33)
VCC_ON: C28.2 C29.2 C41.2 L5.2 U9.1 U10.5 U13.11 X15.1 X25.1 | length 2616.6
  Top w10: U9.1@1449.4,785.06 1449.46,785 U9.1@1475,785 ; v4(1470,620) 1470.43,620.43 C28.2@1470.43,685 ; U13.11@1473.42,433.07 1546.85,433.07 L5.2@1547.24,432.68
  Top w19.68: C28.2@1470.43,685 1675,685 v4(1740,620) 1740,465 1708.07,433.07 C41.2@1633.86,433.07 1633.46,432.68 L5.2@1547.24,432.68 ; U10.5@2186.16,859.46 2186.16,941.87 C29.2@2186.35,942.06 2189.29,945 v1(2245,945)
  Top w20: C28.2@1470.43,685 1470.43,780.43 U9.1@1475,785
  Bottom w10: X15.1@1100.92,746.05 1193.95,746.05 1320,620 v4(1470,620)
  Bottom w19.68: v4(1740,620) 1920,620 v1(2245,945) 2300,945 2338.58,983.58 2338.58,1156.42 2246.04,1248.96 X25.1@2246.04,1324.54
VSTOR: C1.2 C2.2 R20.1 U1.3 U1.19 | length 567.3
  Top w10: R20.1@520.43,280 521.4,279.03 v1(574.03,279.03) ; C2.2@650.43,280 651.4,279.03 v1(695.97,279.03) U1.3@770.07,279.03 ; U1.19@814.36,343.01 v1(814.36,392.5) 825,403.14 C1.2@825,444.57
  Bottom w10: v1(574.03,279.03) v1(695.97,279.03) 700.89,279.03 v1(814.36,392.5)
WU: C31.2 R23.2 R25.2 U9.2 X9.1 | length 537.9
  Top w7.87: U9.2@1449.4,835.06 1501.91,835.06 1515.91,821.06 1515.91,781.06 1535.91,761.06 X9.1@1575.91,761.06 1662.91,761.06 1697.51,795.65 R25.2@1761.91,795.65 C31.2@1841.88,795.65 ; C31.2@1842.88,796.65 R23.2@1919.91,796.65
pads on no net: D3.2 SW1.3 U2.2 U2.3 U2.6 U2.8 U2.16 U2.28 U3.4 U4.2 U4.3 U4.4 U4.5 U4.6 U4.7 U4.14 U4.15 U4.16 U4.17 U4.19 U4.21 U6.3 U6.4 U11.7 U11.11 U11.12 U11.15 U11.16 U13.2 U13.3 U13.4 U13.10 U13.14
copper on no net: | length 3440
  Top w10: 2985,1200 3125,1200 ; 2980,720 3130,720 3130,1360 2980,1360 2980,720
  Bottom w10: 2985,880 3125,880 ; 2980,720 2980,1360 3130,1360 3130,720 2980,720

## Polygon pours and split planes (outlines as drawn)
GND on Top "GND-Top" (solid, remove dead copper, pour order 18): 5,1965 5,5 3145,5 3145,1965
GND on Top "GND_L01_P012" (solid, remove dead copper, pour order 12): 1897.64,66.93 1897.64,433.07 2015.75,433.07 2110.24,433.07 2110.24,496.06 2110.24,842.52 2220.47,842.52 2251.97,842.52 2251.97,724.41 2251.97,240.16 2098.43,240.16 2003.94,240.16 2003.94,86.61 2003.94,66.93 1897.64,66.93
GND on Top "GND_L01_P010" (solid, remove dead copper, pour order 10): 2303.15,728.35 2409.45,728.35 2409.45,43.31 2303.15,43.31 2303.15,728.35
GND on Bottom "GND-Bot" (solid, remove dead copper, pour order 16): 5,1965 3145,1965 3145,5 5,5
GND on GND (split plane): 3137.74,1956.64 3137.74,11.87 11.87,11.87 11.87,1956.64
VCC on Power (split plane): 3137.74,1956.64 3137.74,11.87 11.87,11.87 11.87,1956.64

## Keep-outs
Keep-Out Layer:
  the board outline again, w6

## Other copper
Top:
  region: -239.91,1285.58
  text "1" at 3025,1230 h177.17
Bottom:
  text "4" at 3085,760 h177.17
GND (plane layer: these items are gaps in the copper):
  rectangle: 2975,880 3135,1040
  rectangle: 2975,720 3135,880
  region: 3135,1349.61 2975,1349.61 2975,1200 3135,1200
  text "2" at 2975,1040 h177.17
Power (plane layer: these items are gaps in the copper):
  region: 3135,1200 2975,1200 2975,1040 3135,1040
  rectangle: 2975,1200 3135,1350
  rectangle: 2975,720 3135,880
  text "3" at 2975,880 h177.17

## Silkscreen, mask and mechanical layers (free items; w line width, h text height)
Top Overlay:
  lines w11.81: 330.71,421.26 303.15,421.26 303.15,507.87 330.71,507.87 ; 330.71,534.65 303.15,534.65 303.15,621.27 330.71,621.27
  text "IIS D-ITET" at 460,1840 h118.11
  text "LoRa + WUR" at 1685,1775 h196.85
  text "T" at 2975,1360 h157.48
  text "-" at 240.16,523.62 h29.53
  text "+" at 236.22,444.88 h29.53 r270
  text "May 2017" at 1370,70 h118.11
Bottom Overlay:
  text "B" at 3135,560 h177.17
Top Solder:
  rectangle: 2975,720 3135,1360
  text "-" at 690,630 h60 r180
  text "+" at 950,590 h60
  text "-" at 105,525 h60 r90
  text "+" at 55,405 h60
Bottom Solder:
  rectangle: 2975,720 3135,1360
Mechanical 4:
  the board outline again, w0
Board:
  the board outline again, w6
